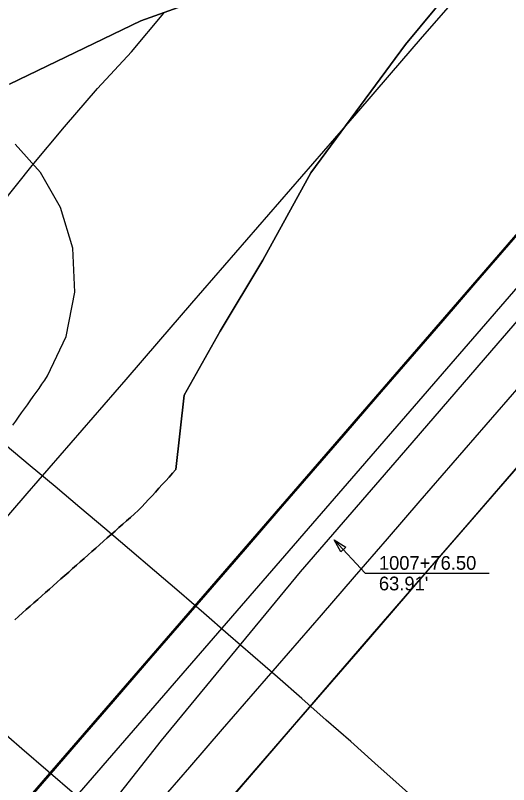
# Model space of a CAD drawing. Extents: x 1006695 to 1009377, y 1883329 to 1886115.
# Drawn here: x 1007824.9 to 1007873.9, y 1884757.7 to 1884834.1 of the extents above; entities that cross this region are included whole.
import ezdxf

# ---------------------------------------------------------------- set-up
doc = ezdxf.new("R2010")
doc.units = 0
for name, color, linetype in [('B_Bottom Cut', 7, 'Continuous'), ('B_Hatch', 7, 'Continuous'), ('R_I-30 Information', 7, 'Continuous'), ('R_No Plot', 7, 'Continuous'), ('R_Prop Const Limits Cut', 7, 'Continuous'), ('R_Prop EOL', 7, 'Continuous'), ('R_Prop EOS I-30', 7, 'Continuous'), ('R_Prop I-30 Guardrail', 7, 'Continuous')]:
    doc.layers.add(name, color=color, linetype=linetype)

msp = doc.modelspace()

# ---------------------------------------------------------------- linework, layer by layer
at = {"layer": 'B_Bottom Cut'}
msp.add_lwpolyline([(1007824.602, 1884793.353), (1007824.891, 1884793.76), (1007825.181, 1884794.168), (1007825.471, 1884794.576), (1007825.76, 1884794.983), (1007826.05, 1884795.391), (1007826.339, 1884795.799), (1007826.629, 1884796.206), (1007826.919, 1884796.614), (1007827.208, 1884797.022), (1007827.498, 1884797.429), (1007827.781, 1884797.841), (1007828.053, 1884798.262), (1007829.907, 1884802.185), (1007830.778, 1884806.594), (1007830.553, 1884810.951), (1007829.353, 1884814.975), (1007827.368, 1884818.454), (1007824.824, 1884821.267)], dxfattribs=at)
at = {"layer": 'B_Hatch'}
for points in [[(1007824.788, 1884774.032), (1007825.171, 1884774.371), (1007825.555, 1884774.71), (1007825.938, 1884775.05), (1007826.322, 1884775.389), (1007826.706, 1884775.728), (1007827.089, 1884776.067), (1007827.473, 1884776.406), (1007827.856, 1884776.745), (1007828.24, 1884777.084), (1007828.624, 1884777.423), (1007829.007, 1884777.762), (1007829.391, 1884778.101), (1007829.774, 1884778.44), (1007830.158, 1884778.78), (1007830.541, 1884779.119), (1007830.925, 1884779.458), (1007831.309, 1884779.797), (1007831.692, 1884780.136), (1007832.076, 1884780.475), (1007832.459, 1884780.814), (1007832.843, 1884781.153), (1007833.226, 1884781.492), (1007833.61, 1884781.831), (1007833.994, 1884782.17), (1007834.377, 1884782.51), (1007834.761, 1884782.849), (1007835.144, 1884783.188), (1007835.528, 1884783.527), (1007835.912, 1884783.866), (1007836.295, 1884784.205), (1007836.679, 1884784.544), (1007837.062, 1884784.883), (1007837.423, 1884785.239), (1007837.762, 1884785.611), (1007838.1, 1884785.983), (1007838.439, 1884786.354), (1007838.778, 1884786.726), (1007839.117, 1884787.098), (1007839.456, 1884787.469), (1007839.795, 1884787.841), (1007840.134, 1884788.213), (1007840.473, 1884788.584), (1007840.814, 1884788.954), (1007841.621, 1884796.347), (1007845.207, 1884802.719), (1007849.449, 1884809.772), (1007854.216, 1884818.419), (1007863.623, 1884831.183), (1007885.302, 1884857.326)], [(1007846.148, 1884836.713), (1007837.328, 1884833.526), (1007824.262, 1884827.234)]]:
    msp.add_lwpolyline(points, dxfattribs=at)
at = {"layer": 'R_I-30 Information'}
for points in [[(1007875.105, 1884843.265), (1007871.832, 1884839.487), (1007868.558, 1884835.708), (1007865.284, 1884831.928), (1007862.01, 1884828.148), (1007858.736, 1884824.369), (1007855.463, 1884820.589), (1007852.189, 1884816.81), (1007848.915, 1884813.031), (1007845.642, 1884809.251), (1007842.368, 1884805.472), (1007839.094, 1884801.693), (1007835.821, 1884797.913), (1007832.546, 1884794.133), (1007829.272, 1884790.353), (1007825.999, 1884786.574), (1007822.726, 1884782.796), (1007819.453, 1884779.017), (1007816.179, 1884775.238), (1007813.22, 1884771.818), (1007809.946, 1884768.039), (1007806.672, 1884764.259), (1007803.144, 1884760.189), (1007799.87, 1884756.41)], [(1007775.84, 1884757.42), (1007779.231, 1884761.097), (1007782.635, 1884764.768), (1007783.743, 1884770.43), (1007786.732, 1884774.456), (1007790.074, 1884779.014), (1007793.039, 1884783.068), (1007796.001, 1884787.126), (1007799.138, 1884789.975), (1007803.175, 1884793.095), (1007807.183, 1884796.239), (1007810.93, 1884799.605), (1007814.032, 1884803.533), (1007817.147, 1884807.45), (1007820.275, 1884811.358), (1007823.412, 1884815.255), (1007826.538, 1884819.162), (1007829.741, 1884823.002), (1007833.002, 1884826.793), (1007836.41, 1884830.456), (1007839.605, 1884834.304)], [(1007877.137, 1884815.065), (1007873.864, 1884811.286), (1007870.59, 1884807.506), (1007867.316, 1884803.727), (1007864.043, 1884799.948), (1007860.769, 1884796.168), (1007857.495, 1884792.389), (1007854.222, 1884788.61), (1007850.948, 1884784.83), (1007847.674, 1884781.051), (1007844.4, 1884777.271), (1007841.127, 1884773.492), (1007837.853, 1884769.713), (1007834.58, 1884765.934), (1007831.306, 1884762.155), (1007828.168, 1884758.53), (1007824.894, 1884754.751)], [(1007874.88, 1884797.185), (1007871.606, 1884793.406), (1007868.333, 1884789.627), (1007865.059, 1884785.848), (1007861.785, 1884782.068), (1007858.512, 1884778.289), (1007855.238, 1884774.509), (1007851.964, 1884770.73), (1007848.691, 1884766.951), (1007845.417, 1884763.172), (1007842.143, 1884759.392), (1007838.87, 1884755.613)], [(1007771.804, 1884670.695), (1007781.631, 1884682.026), (1007791.432, 1884693.378), (1007801.233, 1884704.728), (1007820.909, 1884727.364), (1007830.75, 1884738.684), (1007840.716, 1884749.895), (1007850.54, 1884761.254), (1007860.35, 1884772.598), (1007870.16, 1884783.941), (1007879.97, 1884795.284)], [(1007875.462, 1884790.072), (1007872.191, 1884786.29), (1007868.921, 1884782.508), (1007865.65, 1884778.726), (1007862.379, 1884774.944), (1007859.108, 1884771.162), (1007855.838, 1884767.38), (1007852.567, 1884763.598), (1007849.297, 1884759.816), (1007846.026, 1884756.035)]]:
    msp.add_lwpolyline(points, dxfattribs=at)
at = {"layer": 'R_No Plot'}
msp.add_line((1007860.975, 1884778.664), (1007871.928, 1884778.664), dxfattribs=at)
msp.add_lwpolyline([(1007856.538, 1884781.989), (1007859.612, 1884778.664), (1007860.975, 1884778.664)], dxfattribs=at)
msp.add_lwpolyline([(1007856.538, 1884781.989), (1007857.678, 1884781.243), (1007857.193, 1884780.794)], close=True, dxfattribs=at)
at = {"layer": 'R_Prop Const Limits Cut'}
for points in [[(1007885.302, 1884857.326), (1007863.623, 1884831.183), (1007854.216, 1884818.419), (1007849.449, 1884809.772), (1007845.207, 1884802.719), (1007841.621, 1884796.347), (1007840.814, 1884788.954), (1007840.473, 1884788.584), (1007840.134, 1884788.213), (1007839.795, 1884787.841), (1007839.456, 1884787.469), (1007839.117, 1884787.098), (1007838.778, 1884786.726), (1007838.439, 1884786.354), (1007838.1, 1884785.983), (1007837.762, 1884785.611), (1007837.423, 1884785.239), (1007837.062, 1884784.883), (1007836.679, 1884784.544), (1007836.295, 1884784.205), (1007835.912, 1884783.866), (1007835.528, 1884783.527), (1007835.144, 1884783.188), (1007834.761, 1884782.849), (1007834.377, 1884782.51), (1007833.994, 1884782.17), (1007833.61, 1884781.831), (1007833.226, 1884781.492), (1007832.843, 1884781.153), (1007832.459, 1884780.814), (1007832.076, 1884780.475), (1007831.692, 1884780.136), (1007831.309, 1884779.797), (1007830.925, 1884779.458), (1007830.541, 1884779.119), (1007830.158, 1884778.78), (1007829.774, 1884778.44), (1007829.391, 1884778.101), (1007829.007, 1884777.762), (1007828.624, 1884777.423), (1007828.24, 1884777.084), (1007827.856, 1884776.745), (1007827.473, 1884776.406), (1007827.089, 1884776.067), (1007826.706, 1884775.728), (1007826.322, 1884775.389), (1007825.938, 1884775.05), (1007825.555, 1884774.71), (1007825.171, 1884774.371), (1007824.788, 1884774.032)], [(1007824.262, 1884827.234), (1007837.328, 1884833.526), (1007846.148, 1884836.713)]]:
    msp.add_lwpolyline(points, dxfattribs=at)
at = {"layer": 'R_Prop EOL'}
for radius, start in [(1443.394, 37.045062), (1421.394, 35.651642)]:
    msp.add_arc((1006901.082, 1883681.489), radius, start, 53.471968, dxfattribs=at)
at = {"layer": 'R_Prop EOS I-30'}
msp.add_line((1007796.21, 1884721.79), (1008022.126, 1884982.533), dxfattribs=at)
for points in [[(1008048.152, 1885003.648), (1008039.574, 1884994.322), (1008029.762, 1884982.976), (1008019.955, 1884971.628), (1008010.148, 1884960.283), (1008000.348, 1884948.947), (1007990.535, 1884937.605), (1007980.723, 1884926.262), (1007970.914, 1884914.923), (1007961.096, 1884903.592), (1007951.276, 1884892.259), (1007941.453, 1884880.921), (1007931.637, 1884869.575), (1007921.829, 1884858.223), (1007912.021, 1884846.873), (1007902.216, 1884835.527), (1007892.406, 1884824.185), (1007882.596, 1884812.843), (1007872.785, 1884801.498), (1007862.974, 1884790.155), (1007853.164, 1884778.812), (1007839.352, 1884762.049)], [(1007839.352, 1884762.049), (1007831.129, 1884751.611), (1007798.171, 1884713.865), (1007779.38, 1884692.71)]]:
    msp.add_lwpolyline(points, dxfattribs=at)
at = {"layer": 'R_Prop I-30 Guardrail'}
msp.add_line((1007805.404, 1884727.056), (1008018.223, 1884972.684), dxfattribs=at)

# ---------------------------------------------------------------- texts
at = {"layer": 'R_No Plot'}
for s, p in [('1007+76.50', (1007860.975, 1884779.004)), ("63.91'", (1007860.975, 1884776.96))]:
    msp.add_text(s, height=1.3627, dxfattribs=at).set_placement(p)

doc.saveas('drawing.dxf')
